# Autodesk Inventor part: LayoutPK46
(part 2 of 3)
    geometry: L1 (-25.4, 4.233)-(0, 0); L2 (0, 0)-(-25.4, -4.233); L3 (-25.4, 4.233)-(-25.4, -4.233); L4 (0, 0)-(-25.4, 0); 1 further point
    constraints: 8 end point, 1 midpoint
  sketch "DatumFilled45_3"
    geometry: L1 (0, 25.4)-(0, -25.4); L2 (0, -25.4)-(-25.4, 0); L3 (-25.4, 0)-(0, 25.4); L4 (0, 25.4)-(0, -25.4); L5 (0, -25.4)-(0, 25.4); L6 (0, 25.4)-(-25.4, 0); L7 (-25.4, 0)-(0, 25.4); 1 further point
    constraints: 14 end point
  sketch "Filled-1_3"
    geometry: L1 (-25.4, 0)-(0, 0); L2 (-25.4, -2.527)-(0, 0); L3 (0, 0)-(-25.4, 2.527); L4 (-25.4, 2.527)-(-25.4, -2.527); L5 (-25.4, -2.527)-(0, 0); L6 (0, 0)-(-25.4, -2.527); L7 (-25.4, -2.527)-(-25.4, 2.527); L8 (-25.4, 2.527)-(-25.4, -2.527); L9 (-25.4, -2.527)-(0, 0); L10 (0, 0)-(-25.4, 2.527); L11 (-25.4, 2.527)-(-25.4, -2.527); 1 further point
    constraints: 22 end point, 4 midpoint
  sketch "Borders Default Border_3"
    geometry: L1 (19.05, 12.7)-(19.05, 419.1); L2 (19.05, 419.1)-(539.75, 419.1); L3 (539.75, 419.1)-(539.75, 12.7); L4 (539.75, 12.7)-(19.05, 12.7); L5 (279.4, 6.35)-(279.4, 12.7); L6 (279.4, 12.7)-(277.2, 8.89); L7 (277.2, 8.89)-(281.6, 8.89); L8 (281.6, 8.89)-(279.4, 12.7); L9 (279.4, 425.45)-(279.4, 419.1); L10 (279.4, 419.1)-(277.2, 422.91); L11 (277.2, 422.91)-(281.6, 422.91); L12 (281.6, 422.91)-(279.4, 419.1); L13 (12.7, 215.9)-(19.05, 215.9); L14 (19.05, 215.9)-(15.24, 218.1); L15 (15.24, 218.1)-(15.24, 213.7); L16 (15.24, 213.7)-(19.05, 215.9); L17 (546.1, 215.9)-(539.75, 215.9); L18 (539.75, 215.9)-(543.56, 218.1); L19 (543.56, 218.1)-(543.56, 213.7); L20 (543.56, 213.7)-(539.75, 215.9); L21 (139.7, 12.7)-(139.7, 8.636); L22 (139.7, 419.1)-(139.7, 423.164); L23 (419.1, 12.7)-(419.1, 8.636); L24 (419.1, 419.1)-(419.1, 423.164); L25 (19.05, 107.95)-(14.986, 107.95); L26 (539.75, 107.95)-(543.814, 107.95); L27 (19.05, 323.85)-(14.986, 323.85); L28 (539.75, 323.85)-(543.814, 323.85); 17 further points
    constraints: 56 end point, 8 point on line, 4 midpoint, 16 other
  sketch "GENAXEH_3"
    geometry: L1 (-25.4, 0)-(25.4, 0); 1 further point
    constraints: 2 end point
  sketch "Weldment_3"
    geometry: L1 (-362.49, 605.558)-(-187.308, 59.988); L2 (-48.402, -559.479)-(-89.17, -792.346); L3 (104.596, -840)-(155.018, -682.036); L4 (176.996, -25.915)-(5.037, 246.17); L5 (5.037, 246.17)-(-175.085, 674.867); L6 (-187.308, 59.988)-(-152.339, -48.916); L7 (-104.241, -121.383)-(-75.352, -146.192); L8 (-8.649, -332.41)-(-48.402, -559.479); L9 (155.018, -682.036)-(230.654, -445.083); L10 (-57.997, -88.254)-(-54.949, -85.206); L11 (-57.997, -85.206)-(-54.949, -88.254); C1 r 75 at (0, 0); C2 r 87 at (0, 0); C3 r 45 at (-267.278, 636.131); C4 r 45 at (9.332, -809.591); C5 r 1.524 at (-56.473, -86.73); A1 r 100 centre (-267.278, 636.131) between (-175.085, 674.867) and (-362.49, 605.558); A2 r 100 centre (9.332, -809.591) between (-89.17, -792.346) and (104.596, -840); A3 r 500 centre (-245.668, -293.04) between (250.28, -356.567) and (176.996, -25.915); A4 r 160 centre (0, 0) between (-152.339, -48.916) and (-104.241, -121.383); A5 r 200 centre (-205.653, -297.921) between (-8.649, -332.41) and (-75.352, -146.192); A6 r 500 centre (-245.668, -293.04) between (230.654, -445.083) and (250.28, -356.567); 1 further point
    constraints: 22 end point, 12 point on circle, 11 centre point
  sketch "Connector_3"
    geometry: L1 (157.164, 27.531)-(232.989, 74.957); L2 (483.604, 231.708)-(512.662, 249.882); L3 (76.449, -64.463)-(145.454, 17.372); L4 (449.028, 351.621)-(398.755, 320.177); L5 (509.104, 419.139)-(460.738, 361.78); L6 (526.921, 255.966)-(571.21, 267.162); L7 (232.989, 74.957)-(483.604, 231.708); L8 (398.755, 320.177)-(93.53, 129.27); L9 (529.743, 443.615)-(509.104, 419.139); L10 (79.271, 123.186)-(-24.509, 96.95); L11 (571.21, 267.162)-(630.701, 282.202); L12 (302.321, 205.82)-(305.369, 208.868); L13 (302.321, 208.868)-(305.369, 205.82); C1 r 45 at (0, 0); C2 r 45 at (606.192, 379.152); C3 r 1.524 at (303.845, 207.344); A1 r 50 centre (539.176, 207.491) between (526.921, 255.966) and (512.662, 249.882); A2 r 50 centre (183.678, -14.86) between (157.164, 27.531) and (145.454, 17.372); A3 r 50 centre (422.514, 394.012) between (449.028, 351.621) and (460.738, 361.78); A4 r 50 centre (67.016, 171.661) between (79.271, 123.186) and (93.53, 129.27); A5 r 100 centre (606.192, 379.152) between (630.701, 282.202) and (529.743, 443.615); A6 r 100 centre (0, 0) between (-24.509, 96.95) and (76.449, -64.463); 1 further point
    constraints: 26 end point, 12 point on circle, 9 centre point
  sketch "Base_3"
    geometry: L1 (278.529, -481.687)-(299.453, -447.453); L2 (295.917, -416.857)-(172.052, -291.319); L3 (95.022, -681.286)-(272.857, -489.184); L4 (108.329, 19.101)-(158.403, -264.884); L5 (-225.117, -660.979)-(-108.413, 18.617); L6 (-225.235, -722.613)-(-225.117, -660.979); L7 (-198.661, -766.881)-(-24.713, -859.13); L8 (3.19, -856.093)-(33.762, -830.109); L9 (48.097, -808.832)-(84.242, -699.551); L10 (0, 254)-(0, -254); L11 (-254, 0)-(254, 0); L12 (0, -346)-(0, -854); L13 (-254, -600)-(254, -600); L14 (37.419, -377.546)-(40.467, -374.498); L15 (37.419, -374.498)-(40.467, -377.546); C1 r 40 at (0, -600); C2 r 40 at (0, 0); C3 r 1.524 at (38.943, -376.022); A1 r 47.5 centre (238, -456.916) between (272.857, -489.184) and (278.529, -481.687); A2 r 25 centre (278.122, -434.416) between (299.453, -447.453) and (295.917, -416.857); A3 r 50 centre (207.644, -256.202) between (158.403, -264.884) and (172.052, -291.319); A4 r 50 centre (-175.235, -722.709) between (-225.235, -722.613) and (-198.661, -766.881); A5 r 50 centre (131.713, -715.252) between (95.022, -681.286) and (84.242, -699.551); A6 r 110 centre (0, 0) between (108.329, 19.101) and (-108.413, 18.617); A7 r 25 centre (-13, -837.043) between (-24.713, -859.13) and (3.19, -856.093); A8 r 47.5 centre (3, -793.916) between (33.762, -830.109) and (48.097, -808.832); 1 further point
    constraints: 30 end point, 16 point on circle, 11 centre point
  sketch "CenterSpan_3"
    geometry: L1 (273.969, -185.044)-(234.974, -284.945); L2 (36.362, 93.155)-(259.933, 5.887); L3 (12.317, -103.462)-(-16.542, -98.622); L4 (180.828, -183.299)-(-38.18, -97.813); L5 (437.598, -26.221)-(296.603, -162.71); L6 (-23.266, 102.39)-(214.339, 156.38); L7 (495.815, 30.136)-(437.598, -26.221); L8 (214.339, 156.38)-(404.104, 199.5); L9 (110.262, -93.996)-(113.31, -90.948); L10 (110.262, -90.948)-(113.31, -93.996); C1 r 82 at (0, 0); C2 r 82 at (223.572, -87.268); C3 r 50 at (426.262, 101.986); C4 r 58.472 at (158.121, -254.947); C5 r 1.524 at (111.786, -92.472); A1 r 90 centre (-2.571, -192.223) between (81.268, -224.948) and (12.317, -103.462); A2 r 60 centre (329.862, -206.861) between (290.003, -162.013) and (273.969, -185.044); A3 r 100 centre (223.572, -87.267) between (290.003, -162.013) and (259.933, 5.887); A4 r 100 centre (0, 0) between (36.362, 93.155) and (-16.542, -98.622); A5 r 105 centre (223.572, -87.268) between (189.942, -186.736) and (296.603, -162.71); A6 r 105 centre (0, 0) between (-23.266, 102.39) and (-38.18, -97.813); A7 r 100 centre (426.262, 101.986) between (495.815, 30.136) and (404.104, 199.5); A8 r 82.5 centre (158.121, -254.946) between (81.268, -224.948) and (234.974, -284.944); 1 further point
    constraints: 20 end point, 17 point on circle, 13 centre point, 1 point on line
  sketch "Arm_3"
    geometry: L1 (-25.496, -107.005)-(137.409, -145.82); L2 (2597.068, -901.099)-(2521.421, -896.025); L3 (2257.231, -771.408)-(2076.35, -579.673); L4 (2076.35, -579.673)-(2063.205, -583.463); L5 (2043.846, -578.704)-(1704.981, -254.849); L6 (1379.251, -95.221)-(16.283, 108.788); L7 (137.409, -145.82)-(1374.243, -440.518); L8 (1601.431, -691.827)-(2199.578, -1052.198); L9 (2469.644, -1123.775)-(2592.355, -1120.82); L10 (1293.329, -509.09)-(1296.377, -506.042); L11 (1293.329, -506.042)-(1296.377, -509.09); C1 r 40.528 at (0, 0); C2 r 40.528 at (2589.706, -1010.852); C3 r 1.524 at (1294.853, -507.566); A1 r 400 centre (2548.19, -496.921) between (2482.623, -891.511) and (2521.421, -896.025); A2 r 110 centre (2589.706, -1010.852) between (2597.994, -1120.539) and (2597.068, -901.099); A3 r 400 centre (2548.19, -496.921) between (2257.231, -771.408) and (2482.623, -891.511); A4 r 20 centre (2057.664, -564.246) between (2043.846, -578.704) and (2063.205, -583.463); A5 r 600 centre (1290.432, -688.61) between (1704.981, -254.849) and (1379.251, -95.221); A6 r 70 centre (1358.018, -508.612) between (1423.227, -534.065) and (1374.243, -440.518); A7 r 100 centre (1516.382, -570.427) between (1423.227, -534.065) and (1519.438, -670.38); A8 r 150 centre (1524.023, -820.31) between (1601.431, -691.827) and (1519.438, -670.38); A9 r 500 centre (2457.606, -623.92) between (2199.578, -1052.198) and (2469.644, -1123.775); A10 r 110 centre (0, 0) between (16.283, 108.788) and (-25.496, -107.005); 1 further point
    constraints: 22 end point, 20 point on circle, 13 centre point
  sketch "Bucket_3"
    geometry: L1 (1144.623, -207.025)-(503.799, -207.025); L2 (963.799, -174.025)-(963.799, -170.025); L3 (503.799, -196.903)-(503.799, -206.906); L4 (503.799, -221.903)-(288.457, -221.903); L5 (288.457, -221.903)-(267.908, -192.554); L6 (513.799, -197.025)-(503.799, -197.025); L7 (1243.799, -187.025)-(1243.799, -177.025); L8 (963.799, -187.025)-(963.799, -162.025); L9 (1144.623, -187.025)-(963.799, -187.025); L10 (963.799, -162.025)-(1213.799, -162.025); L11 (1243.799, -177.025)-(1213.799, -162.025); L12 (787.944, 394.043)-(1129.277, -162.025); L13 (284.259, 704.207)-(293.142, 639.189); L14 (628.799, 940.975)-(308.602, 754.162); L15 (-31.849, -105.289)-(98.676, -144.771); L16 (-48.306, 170.395)-(-101.577, 42.215); L17 (226.161, 631.111)-(211.811, 610.911); L18 (291.393, 651.987)-(226.161, 631.111); L19 (-139.649, 366.255)-(98.676, -144.771); L20 (513.799, -197.025)-(1144.623, -197.025); L21 (513.799, -187.025)-(1144.623, -187.025); L22 (531.254, 866.512)-(201.253, 473.232); L23 (537.781, 858.733)-(208.914, 466.804); L24 (1144.623, -207.025)-(1144.623, -197.025); L25 (1144.623, -197.025)-(1144.623, -187.025); L26 (787.944, 394.043)-(636.196, 915.553); L27 (633.32, 925.44)-(628.799, 940.975); L28 (725.404, 1012.893)-(719.482, 979.31); L29 (735.252, 1011.157)-(729.33, 977.574); L30 (714.634, 972.387)-(531.254, 866.512); L31 (725.404, 1012.893)-(735.252, 1011.157); L32 (1144.623, -187.025)-(1243.799, -187.025); L33 (537.781, 858.733)-(719.634, 963.726); L34 (503.799, -221.903)-(503.799, -206.906); L35 (453.565, -192.554)-(144.85, -192.554); L36 (110.864, -170.904)-(98.676, -144.771); L37 (-78.971, 509.811)-(360.018, 662.44); C1 r 25 at (333.799, 710.975); C2 r 45 at (-44.489, 410.635); A1 r 50 centre (333.799, 710.975) between (308.602, 754.162) and (284.259, 704.207); A2 r 40 centre (0, 0) between (13.62, 37.61) and (37.567, -13.738); A3 r 110 centre (0, 0) between (-101.577, 42.215) and (-31.849, -105.289); A4 r 105 centre (-44.489, 410.635) between (-78.971, 509.811) and (-139.649, 366.255); A5 r 408 centre (513.799, 210.975) between (201.253, 473.232) and (513.799, -197.025); A6 r 398 centre (513.799, 210.975) between (208.914, 466.804) and (513.799, -187.025); A7 r 37.5 centre (144.85, -155.054) between (110.864, -170.904) and (144.85, -192.554); A8 r 10 centre (709.634, 981.047) between (714.634, 972.387) and (719.482, 979.31); A9 r 20 centre (709.634, 981.047) between (719.634, 963.726) and (729.33, 977.574); 1 further point
    constraints: 74 end point, 20 point on circle, 16 point on line, 11 centre point
  sketch "FrontBucket_3"
    geometry: L1 (36.508, 713.207)-(-16.797, 670.2); L2 (-16.797, 670.2)-(-101.739, 335.484); L3 (-101.739, 335.484)-(-109.966, 2.719); L4 (8.288, -109.687)-(308.835, -86.978); L5 (308.835, -86.978)-(319.542, -83.051); L6 (19.324, 520.756)-(99.155, 741.781); L7 (99.155, 741.781)-(80.344, 748.575); L8 (80.344, 748.575)-(36.508, 713.207); L9 (1233.625, 258.517)-(1200.234, 261.682); L10 (1200.234, 261.682)-(1143.868, 239.874); L11 (1143.868, 239.874)-(1177.667, 236.867); L12 (1177.667, 236.867)-(1233.625, 258.517); L13 (967.076, 171.475)-(1143.868, 239.874); L14 (1181.276, 227.541)-(976.097, 148.159); L15 (976.097, 148.159)-(967.076, 171.475); L16 (1237.234, 249.191)-(1233.625, 258.517); L17 (1177.667, 236.867)-(1181.276, 227.541); L18 (1181.276, 227.541)-(1237.234, 249.191); L19 (332.219, -99.88)-(327.869, -88.635); L20 (332.219, -99.88)-(340.093, -96.834); L21 (327.869, -88.635)-(326.446, -84.958); L22 (630.662, 15.585)-(695.946, 40.843); L23 (340.093, -96.834)-(630.662, 15.585); L24 (971.406, 160.283)-(964.544, 144.762); L25 (971.406, 160.283)-(969.963, 164.014); L26 (695.946, 40.843)-(690.173, 55.765); L27 (969.963, 164.014)-(690.173, 55.765); L28 (695.946, 40.843)-(964.544, 144.762); L29 (271.723, 1081.905)-(246.908, 1104.472); L30 (246.908, 1104.472)-(15.69, 814.708); L31 (11.012, 759.335)-(43.462, 700.624); L32 (47.21, 660.849)-(-0.759, 514.651); L33 (556.412, -14.214)-(696.307, 39.911); L34 (696.307, 39.911)-(695.946, 40.843); L35 (594.585, 649.257)-(271.723, 1081.905); L36 (459.694, 596.673)-(459.353, 596.937); L37 (459.353, 596.937)-(498.23, 611.978); L38 (1112.062, 227.901)-(576.694, 642.28); L39 (995.062, 182.294)-(998.041, 183.455); L40 (499.228, 612.083)-(459.694, 596.673); L41 (459.694, 596.673)-(526.939, 544.624); L42 (606.946, 482.699)-(686.952, 420.773); L43 (766.958, 358.848)-(846.965, 296.922); L44 (926.971, 234.997)-(985.819, 189.448); L45 (995.055, 182.3)-(995.062, 182.294); L46 (998.041, 183.455)-(1130.882, 235.237); L47 (985.819, 189.448)-(995.055, 182.3); L48 (1130.882, 235.237)-(595.514, 649.616); C1 r 60 at (0, 0); C2 r 85 at (-189.66, 366.918); C3 r 25 at (54.772, 783.522); C4 r 62.5 at (-189.66, 366.918); A1 r 110 centre (0, 0) between (-109.966, 2.719) and (8.288, -109.687); A2 r 408 centre (403.06, 382.155) between (19.324, 520.756) and (16.94, 513.969); A3 r 50 centre (54.772, 783.522) between (15.69, 814.708) and (11.012, 759.335); A4 r 50 centre (-0.298, 676.437) between (47.21, 660.849) and (43.462, 700.624); A5 r 425 centre (403.06, 382.155) between (-0.759, 514.651) and (556.412, -14.214); 1 further point
    constraints: 96 end point, 10 point on circle, 9 centre point, 6 point on line
  sketch "A$C70327705_2"
    geometry: L1 (1293.342, 14.877)-(652.519, 14.877); L2 (1112.519, 47.877)-(1112.519, 51.877); L3 (652.519, 25)-(652.519, 14.997); L4 (652.519, 0)-(437.177, 0); L5 (437.177, 0)-(416.627, 29.348); L6 (662.519, 24.877)-(652.519, 24.877); L7 (1392.519, 34.877)-(1392.519, 44.877); L8 (1112.519, 34.877)-(1112.519, 59.877); L9 (1293.342, 34.877)-(1112.519, 34.877); L10 (1112.519, 59.877)-(1362.519, 59.877); L11 (1392.519, 44.877)-(1362.519, 59.877); L12 (936.663, 615.946)-(1277.997, 59.877); L13 (432.979, 926.11)-(441.861, 861.091); L14 (777.519, 1162.877)-(457.322, 976.064); L15 (116.871, 116.614)-(247.396, 77.132); L16 (100.413, 392.297)-(47.142, 264.117); L17 (374.881, 853.013)-(360.531, 832.814); L18 (440.113, 873.889)-(374.881, 853.013); L19 (9.07, 588.157)-(247.396, 77.132); L20 (662.519, 24.877)-(1293.342, 24.877); L21 (662.519, 34.877)-(1293.342, 34.877); L22 (679.974, 1088.415)-(349.973, 695.135); L23 (686.501, 1080.636)-(357.633, 688.707); L24 (1293.342, 14.877)-(1293.342, 24.877); L25 (1293.342, 24.877)-(1293.342, 34.877); L26 (936.663, 615.946)-(784.916, 1137.456); L27 (782.039, 1147.342)-(777.519, 1162.877); L28 (874.123, 1234.796)-(868.202, 1201.213); L29 (883.971, 1233.059)-(878.05, 1199.476); L30 (863.354, 1194.289)-(679.974, 1088.415); L31 (874.123, 1234.796)-(883.971, 1233.059); L32 (1293.342, 34.877)-(1392.519, 34.877); L33 (686.501, 1080.636)-(868.354, 1185.629); L34 (652.519, 0)-(652.519, 14.997); L35 (602.285, 29.348)-(293.569, 29.348); L36 (259.584, 50.998)-(247.396, 77.132); L37 (69.748, 731.714)-(508.737, 884.343); C1 r 25 at (482.519, 932.877); C2 r 45 at (104.231, 632.537); A1 r 50 centre (482.519, 932.877) between (457.322, 976.064) and (432.979, 926.11); A2 r 40 centre (148.72, 221.902) between (162.34, 259.512) and (186.286, 208.165); A3 r 110 centre (148.72, 221.902) between (47.142, 264.117) and (116.871, 116.614); A4 r 105 centre (104.231, 632.537) between (69.748, 731.714) and (9.07, 588.157); A5 r 408 centre (662.519, 432.877) between (349.973, 695.135) and (662.519, 24.877); A6 r 398 centre (662.519, 432.877) between (357.633, 688.707) and (662.519, 34.877); A7 r 37.5 centre (293.569, 66.848) between (259.584, 50.998) and (293.569, 29.348); A8 r 10 centre (858.354, 1202.949) between (863.354, 1194.289) and (868.202, 1201.213); A9 r 20 centre (858.354, 1202.949) between (868.354, 1185.629) and (878.05, 1199.476); 1 further point
    constraints: 74 end point, 20 point on circle, 16 point on line, 11 centre point
  sketch "A$C60B60B97_2"
    geometry: 1 further point
  sketch "Borders Default Border_9.00X_3"
    geometry: L1 (171.45, 114.3)-(171.45, 3771.9); L2 (171.45, 3771.9)-(4857.75, 3771.9); L3 (4857.75, 3771.9)-(4857.75, 114.3); L4 (4857.75, 114.3)-(171.45, 114.3); L5 (2514.6, 57.15)-(2514.6, 114.3); L6 (2514.6, 114.3)-(2494.803, 80.01); L7 (2494.803, 80.01)-(2534.397, 80.01); L8 (2534.397, 80.01)-(2514.6, 114.3); L9 (2514.6, 3829.05)-(2514.6, 3771.9); L10 (2514.6, 3771.9)-(2494.803, 3806.19); L11 (2494.803, 3806.19)-(2534.397, 3806.19); L12 (2534.397, 3806.19)-(2514.6, 3771.9); L13 (114.3, 1943.1)-(171.45, 1943.1); L14 (171.45, 1943.1)-(137.16, 1962.897); L15 (137.16, 1962.897)-(137.16, 1923.303); L16 (137.16, 1923.303)-(171.45, 1943.1); L17 (4914.9, 1943.1)-(4857.75, 1943.1); L18 (4857.75, 1943.1)-(4892.04, 1962.897); L19 (4892.04, 1962.897)-(4892.04, 1923.303); L20 (4892.04, 1923.303)-(4857.75, 1943.1); L21 (1257.3, 114.3)-(1257.3, 77.724); L22 (1257.3, 3771.9)-(1257.3, 3808.476); L23 (3771.9, 114.3)-(3771.9, 77.724); L24 (3771.9, 3771.9)-(3771.9, 3808.476); L25 (171.45, 971.55)-(134.874, 971.55); L26 (4857.75, 971.55)-(4894.326, 971.55); L27 (171.45, 2914.65)-(134.874, 2914.65); L28 (4857.75, 2914.65)-(4894.326, 2914.65); 17 further points
    constraints: 56 end point, 8 point on line, 4 midpoint, 16 other
  sketch "_Closed_4"
    geometry: L1 (-25.4, 4.233)-(0, 0); L2 (0, 0)-(-25.4, -4.233); L3 (-25.4, 4.233)-(-25.4, -4.233); L4 (0, 0)-(-25.4, 0); 1 further point
    constraints: 8 end point, 1 midpoint
  sketch "DatumFilled45_4"
    geometry: L1 (0, 25.4)-(0, -25.4); L2 (0, -25.4)-(-25.4, 0); L3 (-25.4, 0)-(0, 25.4); L4 (0, 25.4)-(0, -25.4); L5 (0, -25.4)-(0, 25.4); L6 (0, 25.4)-(-25.4, 0); L7 (-25.4, 0)-(0, 25.4); 1 further point
    constraints: 14 end point
  sketch "Filled-1_4"
    geometry: L1 (-25.4, 0)-(0, 0); L2 (-25.4, -2.527)-(0, 0); L3 (0, 0)-(-25.4, 2.527); L4 (-25.4, 2.527)-(-25.4, -2.527); L5 (-25.4, -2.527)-(0, 0); L6 (0, 0)-(-25.4, -2.527); L7 (-25.4, -2.527)-(-25.4, 2.527); L8 (-25.4, 2.527)-(-25.4, -2.527); L9 (-25.4, -2.527)-(0, 0); L10 (0, 0)-(-25.4, 2.527); L11 (-25.4, 2.527)-(-25.4, -2.527); 1 further point
    constraints: 22 end point, 4 midpoint
  sketch "Borders Default Border_4"
    geometry: L1 (19.05, 12.7)-(19.05, 419.1); L2 (19.05, 419.1)-(539.75, 419.1); L3 (539.75, 419.1)-(539.75, 12.7); L4 (539.75, 12.7)-(19.05, 12.7); L5 (279.4, 6.35)-(279.4, 12.7); L6 (279.4, 12.7)-(277.2, 8.89); L7 (277.2, 8.89)-(281.6, 8.89); L8 (281.6, 8.89)-(279.4, 12.7); L9 (279.4, 425.45)-(279.4, 419.1); L10 (279.4, 419.1)-(277.2, 422.91); L11 (277.2, 422.91)-(281.6, 422.91); L12 (281.6, 422.91)-(279.4, 419.1); L13 (12.7, 215.9)-(19.05, 215.9); L14 (19.05, 215.9)-(15.24, 218.1); L15 (15.24, 218.1)-(15.24, 213.7); L16 (15.24, 213.7)-(19.05, 215.9); L17 (546.1, 215.9)-(539.75, 215.9); L18 (539.75, 215.9)-(543.56, 218.1); L19 (543.56, 218.1)-(543.56, 213.7); L20 (543.56, 213.7)-(539.75, 215.9); L21 (139.7, 12.7)-(139.7, 8.636); L22 (139.7, 419.1)-(139.7, 423.164); L23 (419.1, 12.7)-(419.1, 8.636); L24 (419.1, 419.1)-(419.1, 423.164); L25 (19.05, 107.95)-(14.986, 107.95); L26 (539.75, 107.95)-(543.814, 107.95); L27 (19.05, 323.85)-(14.986, 323.85); L28 (539.75, 323.85)-(543.814, 323.85); 17 further points
    constraints: 56 end point, 8 point on line, 4 midpoint, 16 other
  sketch "GENAXEH_4"
    geometry: L1 (-25.4, 0)-(25.4, 0); 1 further point
    constraints: 2 end point
  sketch "Weldment_4"
    geometry: L1 (-362.49, 605.558)-(-187.308, 59.988); L2 (-48.402, -559.479)-(-89.17, -792.346); L3 (104.596, -840)-(155.018, -682.036); L4 (176.996, -25.915)-(5.037, 246.17); L5 (5.037, 246.17)-(-175.085, 674.867); L6 (-187.308, 59.988)-(-152.339, -48.916); L7 (-104.241, -121.383)-(-75.352, -146.192); L8 (-8.649, -332.41)-(-48.402, -559.479); L9 (155.018, -682.036)-(230.654, -445.083); L10 (-57.997, -88.254)-(-54.949, -85.206); L11 (-57.997, -85.206)-(-54.949, -88.254); C1 r 75 at (0, 0); C2 r 87 at (0, 0); C3 r 45 at (-267.278, 636.131); C4 r 45 at (9.332, -809.591); C5 r 1.524 at (-56.473, -86.73); A1 r 100 centre (-267.278, 636.131) between (-175.085, 674.867) and (-362.49, 605.558); A2 r 100 centre (9.332, -809.591) between (-89.17, -792.346) and (104.596, -840); A3 r 500 centre (-245.668, -293.04) between (250.28, -356.567) and (176.996, -25.915); A4 r 160 centre (0, 0) between (-152.339, -48.916) and (-104.241, -121.383); A5 r 200 centre (-205.653, -297.921) between (-8.649, -332.41) and (-75.352, -146.192); A6 r 500 centre (-245.668, -293.04) between (230.654, -445.083) and (250.28, -356.567); 1 further point
    constraints: 22 end point, 12 point on circle, 11 centre point
  sketch "Connector_4"
    geometry: L1 (157.164, 27.531)-(232.989, 74.957); L2 (483.604, 231.708)-(512.662, 249.882); L3 (76.449, -64.463)-(145.454, 17.372); L4 (449.028, 351.621)-(398.755, 320.177); L5 (509.104, 419.139)-(460.738, 361.78); L6 (526.921, 255.966)-(571.21, 267.162); L7 (232.989, 74.957)-(483.604, 231.708); L8 (398.755, 320.177)-(93.53, 129.27); L9 (529.743, 443.615)-(509.104, 419.139); L10 (79.271, 123.186)-(-24.509, 96.95); L11 (571.21, 267.162)-(630.701, 282.202); L12 (302.321, 205.82)-(305.369, 208.868); L13 (302.321, 208.868)-(305.369, 205.82); C1 r 45 at (0, 0); C2 r 45 at (606.192, 379.152); C3 r 1.524 at (303.845, 207.344); A1 r 50 centre (539.176, 207.491) between (526.921, 255.966) and (512.662, 249.882); A2 r 50 centre (183.678, -14.86) between (157.164, 27.531) and (145.454, 17.372); A3 r 50 centre (422.514, 394.012) between (449.028, 351.621) and (460.738, 361.78); A4 r 50 centre (67.016, 171.661) between (79.271, 123.186) and (93.53, 129.27); A5 r 100 centre (606.192, 379.152) between (630.701, 282.202) and (529.743, 443.615); A6 r 100 centre (0, 0) between (-24.509, 96.95) and (76.449, -64.463); 1 further point
    constraints: 26 end point, 12 point on circle, 9 centre point
  sketch "Base_4"
    geometry: L1 (278.529, -481.687)-(299.453, -447.453); L2 (295.917, -416.857)-(172.052, -291.319); L3 (95.022, -681.286)-(272.857, -489.184); L4 (108.329, 19.101)-(158.403, -264.884); L5 (-225.117, -660.979)-(-108.413, 18.617); L6 (-225.235, -722.613)-(-225.117, -660.979); L7 (-198.661, -766.881)-(-24.713, -859.13); L8 (3.19, -856.093)-(33.762, -830.109); L9 (48.097, -808.832)-(84.242, -699.551); L10 (0, 254)-(0, -254); L11 (-254, 0)-(254, 0); L12 (0, -346)-(0, -854); L13 (-254, -600)-(254, -600); L14 (37.419, -377.546)-(40.467, -374.498); L15 (37.419, -374.498)-(40.467, -377.546); C1 r 40 at (0, -600); C2 r 40 at (0, 0); C3 r 1.524 at (38.943, -376.022); A1 r 47.5 centre (238, -456.916) between (272.857, -489.184) and (278.529, -481.687); A2 r 25 centre (278.122, -434.416) between (299.453, -447.453) and (295.917, -416.857); A3 r 50 centre (207.644, -256.202) between (158.403, -264.884) and (172.052, -291.319); A4 r 50 centre (-175.235, -722.709) between (-225.235, -722.613) and (-198.661, -766.881); A5 r 50 centre (131.713, -715.252) between (95.022, -681.286) and (84.242, -699.551); A6 r 110 centre (0, 0) between (108.329, 19.101) and (-108.413, 18.617); A7 r 25 centre (-13, -837.043) between (-24.713, -859.13) and (3.19, -856.093); A8 r 47.5 centre (3, -793.916) between (33.762, -830.109) and (48.097, -808.832); 1 further point
    constraints: 30 end point, 16 point on circle, 11 centre point
  sketch "CenterSpan_4"
    geometry: L1 (273.969, -185.044)-(234.974, -284.945); L2 (36.362, 93.155)-(259.933, 5.887); L3 (12.317, -103.462)-(-16.542, -98.622); L4 (180.828, -183.299)-(-38.18, -97.813); L5 (437.598, -26.221)-(296.603, -162.71); L6 (-23.266, 102.39)-(214.339, 156.38); L7 (495.815, 30.136)-(437.598, -26.221); L8 (214.339, 156.38)-(404.104, 199.5); L9 (110.262, -93.996)-(113.31, -90.948); L10 (110.262, -90.948)-(113.31, -93.996); C1 r 82 at (0, 0); C2 r 82 at (223.572, -87.268); C3 r 50 at (426.262, 101.986); C4 r 58.472 at (158.121, -254.947); C5 r 1.524 at (111.786, -92.472); A1 r 90 centre (-2.571, -192.223) between (81.268, -224.948) and (12.317, -103.462); A2 r 60 centre (329.862, -206.861) between (290.003, -162.013) and (273.969, -185.044); A3 r 100 centre (223.572, -87.267) between (290.003, -162.013) and (259.933, 5.887); A4 r 100 centre (0, 0) between (36.362, 93.155) and (-16.542, -98.622); A5 r 105 centre (223.572, -87.268) between (189.942, -186.736) and (296.603, -162.71); A6 r 105 centre (0, 0) between (-23.266, 102.39) and (-38.18, -97.813); A7 r 100 centre (426.262, 101.986) between (495.815, 30.136) and (404.104, 199.5); A8 r 82.5 centre (158.121, -254.946) between (81.268, -224.948) and (234.974, -284.944); 1 further point
    constraints: 20 end point, 17 point on circle, 13 centre point, 1 point on line
  sketch "Arm_4"
    geometry: L1 (-25.496, -107.005)-(137.409, -145.82); L2 (2597.068, -901.099)-(2521.421, -896.025); L3 (2257.231, -771.408)-(2076.35, -579.673); L4 (2076.35, -579.673)-(2063.205, -583.463); L5 (2043.846, -578.704)-(1704.981, -254.849); L6 (1379.251, -95.221)-(16.283, 108.788); L7 (137.409, -145.82)-(1374.243, -440.518); L8 (1601.431, -691.827)-(2199.578, -1052.198); L9 (2469.644, -1123.775)-(2592.355, -1120.82); L10 (1293.329, -509.09)-(1296.377, -506.042); L11 (1293.329, -506.042)-(1296.377, -509.09); C1 r 40.528 at (0, 0); C2 r 40.528 at (2589.706, -1010.852); C3 r 1.524 at (1294.853, -507.566); A1 r 400 centre (2548.19, -496.921) between (2482.623, -891.511) and (2521.421, -896.025); A2 r 110 centre (2589.706, -1010.852) between (2597.994, -1120.539) and (2597.068, -901.099); A3 r 400 centre (2548.19, -496.921) between (2257.231, -771.408) and (2482.623, -891.511); A4 r 20 centre (2057.664, -564.246) between (2043.846, -578.704) and (2063.205, -583.463); A5 r 600 centre (1290.432, -688.61) between (1704.981, -254.849) and (1379.251, -95.221); A6 r 70 centre (1358.018, -508.612) between (1423.227, -534.065) and (1374.243, -440.518); A7 r 100 centre (1516.382, -570.427) between (1423.227, -534.065) and (1519.438, -670.38); A8 r 150 centre (1524.023, -820.31) between (1601.431, -691.827) and (1519.438, -670.38); A9 r 500 centre (2457.606, -623.92) between (2199.578, -1052.198) and (2469.644, -1123.775); A10 r 110 centre (0, 0) between (16.283, 108.788) and (-25.496, -107.005); 1 further point
    constraints: 22 end point, 20 point on circle, 13 centre point
  sketch "Bucket_4"
    geometry: L1 (0, -20)-(-640.824, -20); L2 (-180.824, 13)-(-180.824, 17); L3 (-640.824, -9.877)-(-640.824, -19.88); L4 (-640.824, -34.877)-(-856.165, -34.877); L5 (-856.165, -34.877)-(-876.715, -5.529); L6 (-630.824, -10)-(-640.824, -10); L7 (99.176, 0)-(99.176, 10); L8 (-180.824, 0)-(-180.824, 25); L9 (0, 0)-(-180.824, 0); L10 (-180.824, 25)-(69.176, 25); L11 (99.176, 10)-(69.176, 25); L12 (-356.679, 581.068)-(-15.346, 25); L13 (-860.363, 891.232)-(-851.481, 826.214); L14 (-515.824, 1128)-(-836.02, 941.187); L15 (-1176.471, 81.737)-(-1045.947, 42.254); L16 (-1192.929, 357.42)-(-1246.2, 229.24); L17 (-918.462, 818.136)-(-932.812, 797.937); L18 (-853.23, 839.012)-(-918.462, 818.136); L19 (-1284.272, 553.28)-(-1045.947, 42.254); L20 (-630.824, -10)-(0, -10); L21 (-630.824, 0)-(0, 0); L22 (-613.369, 1053.537)-(-943.37, 660.257); L23 (-606.842, 1045.759)-(-935.709, 653.829); L24 (0, -20)-(0, -10); L25 (0, -10)-(0, 0); L26 (-356.679, 581.068)-(-508.427, 1102.579); L27 (-511.303, 1112.465)-(-515.824, 1128); L28 (-419.219, 1199.918)-(-425.141, 1166.336); L29 (-409.371, 1198.182)-(-415.292, 1164.599); L30 (-429.989, 1159.412)-(-613.369, 1053.537); L31 (-419.219, 1199.918)-(-409.371, 1198.182); L32 (0, 0)-(99.176, 0); L33 (-606.842, 1045.759)-(-424.989, 1150.752); L34 (-640.824, -34.877)-(-640.824, -19.88); L35 (-691.058, -5.529)-(-999.773, -5.529); L36 (-1033.759, 16.121)-(-1045.947, 42.254); L37 (-1223.594, 696.836)-(-784.605, 849.466); C1 r 25 at (-810.824, 898); C2 r 45 at (-1189.112, 597.66); A1 r 50 centre (-810.824, 898) between (-836.02, 941.187) and (-860.363, 891.232); A2 r 40 centre (-1144.623, 187.025) between (-1131.003, 224.635) and (-1107.056, 173.287); A3 r 110 centre (-1144.623, 187.025) between (-1246.2, 229.24) and (-1176.471, 81.737); A4 r 105 centre (-1189.112, 597.66) between (-1223.594, 696.836) and (-1284.272, 553.28); A5 r 408 centre (-630.824, 398) between (-943.37, 660.257) and (-630.824, -10); A6 r 398 centre (-630.824, 398) between (-935.709, 653.829) and (-630.824, 0); A7 r 37.5 centre (-999.773, 31.971) between (-1033.759, 16.121) and (-999.773, -5.529); A8 r 10 centre (-434.989, 1168.072) between (-429.989, 1159.412) and (-425.141, 1166.336); A9 r 20 centre (-434.989, 1168.072) between (-424.989, 1150.752) and (-415.292, 1164.599); 1 further point
    constraints: 74 end point, 20 point on circle, 16 point on line, 11 centre point
  sketch "FrontBucket_4"
    geometry: L1 (36.508, 713.207)-(-16.797, 670.2); L2 (-16.797, 670.2)-(-101.739, 335.484); L3 (-101.739, 335.484)-(-109.966, 2.719); L4 (8.288, -109.687)-(308.835, -86.978); L5 (308.835, -86.978)-(319.542, -83.051); L6 (19.324, 520.756)-(99.155, 741.781); L7 (99.155, 741.781)-(80.344, 748.575); L8 (80.344, 748.575)-(36.508, 713.207); L9 (1233.625, 258.517)-(1200.234, 261.682); L10 (1200.234, 261.682)-(1143.868, 239.874); L11 (1143.868, 239.874)-(1177.667, 236.867); L12 (1177.667, 236.867)-(1233.625, 258.517); L13 (967.076, 171.475)-(1143.868, 239.874); L14 (1181.276, 227.541)-(976.097, 148.159); L15 (976.097, 148.159)-(967.076, 171.475); L16 (1237.234, 249.191)-(1233.625, 258.517); L17 (1177.667, 236.867)-(1181.276, 227.541); L18 (1181.276, 227.541)-(1237.234, 249.191); L19 (332.219, -99.88)-(327.869, -88.635); L20 (332.219, -99.88)-(340.093, -96.834); L21 (327.869, -88.635)-(326.446, -84.958); L22 (630.662, 15.585)-(695.946, 40.843); L23 (340.093, -96.834)-(630.662, 15.585); L24 (971.406, 160.283)-(964.544, 144.762); L25 (971.406, 160.283)-(969.963, 164.014); L26 (695.946, 40.843)-(690.173, 55.765); L27 (969.963, 164.014)-(690.173, 55.765); L28 (695.946, 40.843)-(964.544, 144.762); L29 (271.723, 1081.905)-(246.908, 1104.472); L30 (246.908, 1104.472)-(15.69, 814.708); L31 (11.012, 759.335)-(43.462, 700.624); L32 (47.21, 660.849)-(-0.759, 514.651); L33 (556.412, -14.214)-(696.307, 39.911); L34 (696.307, 39.911)-(695.946, 40.843); L35 (594.585, 649.257)-(271.723, 1081.905); L36 (459.694, 596.673)-(459.353, 596.937); L37 (459.353, 596.937)-(498.23, 611.978); L38 (1112.062, 227.901)-(576.694, 642.28); L39 (995.062, 182.294)-(998.041, 183.455); L40 (499.228, 612.083)-(459.694, 596.673); L41 (459.694, 596.673)-(526.939, 544.624); L42 (606.946, 482.699)-(686.952, 420.773); L43 (766.958, 358.848)-(846.965, 296.922); L44 (926.971, 234.997)-(985.819, 189.448); L45 (995.055, 182.3)-(995.062, 182.294); L46 (998.041, 183.455)-(1130.882, 235.237); L47 (985.819, 189.448)-(995.055, 182.3); L48 (1130.882, 235.237)-(595.514, 649.616); C1 r 60 at (0, 0); C2 r 85 at (-189.66, 366.918); C3 r 25 at (54.772, 783.522); C4 r 62.5 at (-189.66, 366.918); A1 r 110 centre (0, 0) between (-109.966, 2.719) and (8.288, -109.687); A2 r 408 centre (403.06, 382.155) between (19.324, 520.756) and (16.94, 513.969); A3 r 50 centre (54.772, 783.522) between (15.69, 814.708) and (11.012, 759.335); A4 r 50 centre (-0.298, 676.437) between (47.21, 660.849) and (43.462, 700.624); A5 r 425 centre (403.06, 382.155) between (-0.759, 514.651) and (556.412, -14.214); 1 further point
    constraints: 96 end point, 10 point on circle, 9 centre point, 6 point on line
  sketch "A$C70327705_3"
    geometry: L1 (1293.342, 14.877)-(652.519, 14.877); L2 (1112.519, 47.877)-(1112.519, 51.877); L3 (652.519, 25)-(652.519, 14.997); L4 (652.519, 0)-(437.177, 0); L5 (437.177, 0)-(416.627, 29.348); L6 (662.519, 24.877)-(652.519, 24.877); L7 (1392.519, 34.877)-(1392.519, 44.877); L8 (1112.519, 34.877)-(1112.519, 59.877); L9 (1293.342, 34.877)-(1112.519, 34.877); L10 (1112.519, 59.877)-(1362.519, 59.877); L11 (1392.519, 44.877)-(1362.519, 59.877); L12 (936.663, 615.946)-(1277.997, 59.877); L13 (432.979, 926.11)-(441.861, 861.091); L14 (777.519, 1162.877)-(457.322, 976.064); L15 (116.871, 116.614)-(247.396, 77.132); L16 (100.413, 392.297)-(47.142, 264.117); L17 (374.881, 853.013)-(360.531, 832.814); L18 (440.113, 873.889)-(374.881, 853.013); L19 (9.07, 588.157)-(247.396, 77.132); L20 (662.519, 24.877)-(1293.342, 24.877); L21 (662.519, 34.877)-(1293.342, 34.877); L22 (679.974, 1088.415)-(349.973, 695.135); L23 (686.501, 1080.636)-(357.633, 688.707); L24 (1293.342, 14.877)-(1293.342, 24.877); L25 (1293.342, 24.877)-(1293.342, 34.877); L26 (936.663, 615.946)-(784.916, 1137.456); L27 (782.039, 1147.342)-(777.519, 1162.877); L28 (874.123, 1234.796)-(868.202, 1201.213); L29 (883.971, 1233.059)-(878.05, 1199.476); L30 (863.354, 1194.289)-(679.974, 1088.415); L31 (874.123, 1234.796)-(883.971, 1233.059); L32 (1293.342, 34.877)-(1392.519, 34.877); L33 (686.501, 1080.636)-(868.354, 1185.629); L34 (652.519, 0)-(652.519, 14.997); L35 (602.285, 29.348)-(293.569, 29.348); L36 (259.584, 50.998)-(247.396, 77.132); L37 (69.748, 731.714)-(508.737, 884.343); C1 r 25 at (482.519, 932.877); C2 r 45 at (104.231, 632.537); A1 r 50 centre (482.519, 932.877) between (457.322, 976.064) and (432.979, 926.11); A2 r 40 centre (148.72, 221.902) between (162.34, 259.512) and (186.286, 208.165); A3 r 110 centre (148.72, 221.902) between (47.142, 264.117) and (116.871, 116.614); A4 r 105 centre (104.231, 632.537) between (69.748, 731.714) and (9.07, 588.157); A5 r 408 centre (662.519, 432.877) between (349.973, 695.135) and (662.519, 24.877); A6 r 398 centre (662.519, 432.877) between (357.633, 688.707) and (662.519, 34.877); A7 r 37.5 centre (293.569, 66.848) between (259.584, 50.998) and (293.569, 29.348); A8 r 10 centre (858.354, 1202.949) between (863.354, 1194.289) and (868.202, 1201.213); A9 r 20 centre (858.354, 1202.949) between (868.354, 1185.629) and (878.05, 1199.476); 1 further point
    constraints: 74 end point, 20 point on circle, 16 point on line, 11 centre point
  sketch "A$C60B60B97_3"
    geometry: 1 further point
  sketch "Borders Default Border_9.00X_4"
    geometry: L1 (171.45, 114.3)-(171.45, 3771.9); L2 (171.45, 3771.9)-(4857.75, 3771.9); L3 (4857.75, 3771.9)-(4857.75, 114.3); L4 (4857.75, 114.3)-(171.45, 114.3); L5 (2514.6, 57.15)-(2514.6, 114.3); L6 (2514.6, 114.3)-(2494.803, 80.01); L7 (2494.803, 80.01)-(2534.397, 80.01); L8 (2534.397, 80.01)-(2514.6, 114.3); L9 (2514.6, 3829.05)-(2514.6, 3771.9); L10 (2514.6, 3771.9)-(2494.803, 3806.19); L11 (2494.803, 3806.19)-(2534.397, 3806.19); L12 (2534.397, 3806.19)-(2514.6, 3771.9); L13 (114.3, 1943.1)-(171.45, 1943.1); L14 (171.45, 1943.1)-(137.16, 1962.897); L15 (137.16, 1962.897)-(137.16, 1923.303); L16 (137.16, 1923.303)-(171.45, 1943.1); L17 (4914.9, 1943.1)-(4857.75, 1943.1); L18 (4857.75, 1943.1)-(4892.04, 1962.897); L19 (4892.04, 1962.897)-(4892.04, 1923.303); L20 (4892.04, 1923.303)-(4857.75, 1943.1); L21 (1257.3, 114.3)-(1257.3, 77.724); L22 (1257.3, 3771.9)-(1257.3, 3808.476); L23 (3771.9, 114.3)-(3771.9, 77.724); L24 (3771.9, 3771.9)-(3771.9, 3808.476); L25 (171.45, 971.55)-(134.874, 971.55); L26 (4857.75, 971.55)-(4894.326, 971.55); L27 (171.45, 2914.65)-(134.874, 2914.65); L28 (4857.75, 2914.65)-(4894.326, 2914.65); 17 further points
    constraints: 56 end point, 8 point on line, 4 midpoint, 16 other
  sketch "_Closed_5"
    geometry: L1 (-25.4, 4.233)-(0, 0); L2 (0, 0)-(-25.4, -4.233); L3 (-25.4, 4.233)-(-25.4, -4.233); L4 (0, 0)-(-25.4, 0); 1 further point
    constraints: 8 end point, 1 midpoint
  sketch "DatumFilled45_5"
    geometry: L1 (0, 25.4)-(0, -25.4); L2 (0, -25.4)-(-25.4, 0); L3 (-25.4, 0)-(0, 25.4); L4 (0, 25.4)-(0, -25.4); L5 (0, -25.4)-(0, 25.4); L6 (0, 25.4)-(-25.4, 0); L7 (-25.4, 0)-(0, 25.4); 1 further point
    constraints: 14 end point
  sketch "Filled-1_5"
    geometry: L1 (-25.4, 0)-(0, 0); L2 (-25.4, -2.527)-(0, 0); L3 (0, 0)-(-25.4, 2.527); L4 (-25.4, 2.527)-(-25.4, -2.527); L5 (-25.4, -2.527)-(0, 0); L6 (0, 0)-(-25.4, -2.527); L7 (-25.4, -2.527)-(-25.4, 2.527); L8 (-25.4, 2.527)-(-25.4, -2.527); L9 (-25.4, -2.527)-(0, 0); L10 (0, 0)-(-25.4, 2.527); L11 (-25.4, 2.527)-(-25.4, -2.527); 1 further point
    constraints: 22 end point, 4 midpoint
  sketch "Borders Default Border_5"
    geometry: L1 (19.05, 12.7)-(19.05, 419.1); L2 (19.05, 419.1)-(539.75, 419.1); L3 (539.75, 419.1)-(539.75, 12.7); L4 (539.75, 12.7)-(19.05, 12.7); L5 (279.4, 6.35)-(279.4, 12.7); L6 (279.4, 12.7)-(277.2, 8.89); L7 (277.2, 8.89)-(281.6, 8.89); L8 (281.6, 8.89)-(279.4, 12.7); L9 (279.4, 425.45)-(279.4, 419.1); L10 (279.4, 419.1)-(277.2, 422.91); L11 (277.2, 422.91)-(281.6, 422.91); L12 (281.6, 422.91)-(279.4, 419.1); L13 (12.7, 215.9)-(19.05, 215.9); L14 (19.05, 215.9)-(15.24, 218.1); L15 (15.24, 218.1)-(15.24, 213.7); L16 (15.24, 213.7)-(19.05, 215.9); L17 (546.1, 215.9)-(539.75, 215.9); L18 (539.75, 215.9)-(543.56, 218.1); L19 (543.56, 218.1)-(543.56, 213.7); L20 (543.56, 213.7)-(539.75, 215.9); L21 (139.7, 12.7)-(139.7, 8.636); L22 (139.7, 419.1)-(139.7, 423.164); L23 (419.1, 12.7)-(419.1, 8.636); L24 (419.1, 419.1)-(419.1, 423.164); L25 (19.05, 107.95)-(14.986, 107.95); L26 (539.75, 107.95)-(543.814, 107.95); L27 (19.05, 323.85)-(14.986, 323.85); L28 (539.75, 323.85)-(543.814, 323.85); 17 further points
    constraints: 56 end point, 8 point on line, 4 midpoint, 16 other
  sketch "GENAXEH_5"
    geometry: L1 (-25.4, 0)-(25.4, 0); 1 further point
    constraints: 2 end point
  sketch "Weldment_5"
    geometry: L1 (-362.49, 605.558)-(-187.308, 59.988); L2 (-48.402, -559.479)-(-89.17, -792.346); L3 (104.596, -840)-(155.018, -682.036); L4 (176.996, -25.915)-(5.037, 246.17); L5 (5.037, 246.17)-(-175.085, 674.867); L6 (-187.308, 59.988)-(-152.339, -48.916); L7 (-104.241, -121.383)-(-75.352, -146.192); L8 (-8.649, -332.41)-(-48.402, -559.479); L9 (155.018, -682.036)-(230.654, -445.083); L10 (-57.997, -88.254)-(-54.949, -85.206); L11 (-57.997, -85.206)-(-54.949, -88.254); C1 r 75 at (0, 0); C2 r 87 at (0, 0); C3 r 45 at (-267.278, 636.131); C4 r 45 at (9.332, -809.591); C5 r 1.524 at (-56.473, -86.73); A1 r 100 centre (-267.278, 636.131) between (-175.085, 674.867) and (-362.49, 605.558); A2 r 100 centre (9.332, -809.591) between (-89.17, -792.346) and (104.596, -840); A3 r 500 centre (-245.668, -293.04) between (250.28, -356.567) and (176.996, -25.915); A4 r 160 centre (0, 0) between (-152.339, -48.916) and (-104.241, -121.383); A5 r 200 centre (-205.653, -297.921) between (-8.649, -332.41) and (-75.352, -146.192); A6 r 500 centre (-245.668, -293.04) between (230.654, -445.083) and (250.28, -356.567); 1 further point
    constraints: 22 end point, 12 point on circle, 11 centre point
  sketch "Connector_5"
    geometry: L1 (157.164, 27.531)-(232.989, 74.957); L2 (483.604, 231.708)-(512.662, 249.882); L3 (76.449, -64.463)-(145.454, 17.372); L4 (449.028, 351.621)-(398.755, 320.177); L5 (509.104, 419.139)-(460.738, 361.78); L6 (526.921, 255.966)-(571.21, 267.162); L7 (232.989, 74.957)-(483.604, 231.708); L8 (398.755, 320.177)-(93.53, 129.27); L9 (529.743, 443.615)-(509.104, 419.139); L10 (79.271, 123.186)-(-24.509, 96.95); L11 (571.21, 267.162)-(630.701, 282.202); L12 (302.321, 205.82)-(305.369, 208.868); L13 (302.321, 208.868)-(305.369, 205.82); C1 r 45 at (0, 0); C2 r 45 at (606.192, 379.152); C3 r 1.524 at (303.845, 207.344); A1 r 50 centre (539.176, 207.491) between (526.921, 255.966) and (512.662, 249.882); A2 r 50 centre (183.678, -14.86) between (157.164, 27.531) and (145.454, 17.372); A3 r 50 centre (422.514, 394.012) between (449.028, 351.621) and (460.738, 361.78); A4 r 50 centre (67.016, 171.661) between (79.271, 123.186) and (93.53, 129.27); A5 r 100 centre (606.192, 379.152) between (630.701, 282.202) and (529.743, 443.615); A6 r 100 centre (0, 0) between (-24.509, 96.95) and (76.449, -64.463); 1 further point
    constraints: 26 end point, 12 point on circle, 9 centre point
  sketch "Base_5"
    geometry: L1 (278.529, -481.687)-(299.453, -447.453); L2 (295.917, -416.857)-(172.052, -291.319); L3 (95.022, -681.286)-(272.857, -489.184); L4 (108.329, 19.101)-(158.403, -264.884); L5 (-225.117, -660.979)-(-108.413, 18.617); L6 (-225.235, -722.613)-(-225.117, -660.979); L7 (-198.661, -766.881)-(-24.713, -859.13); L8 (3.19, -856.093)-(33.762, -830.109); L9 (48.097, -808.832)-(84.242, -699.551); L10 (0, 254)-(0, -254); L11 (-254, 0)-(254, 0); L12 (0, -346)-(0, -854); L13 (-254, -600)-(254, -600); L14 (37.419, -377.546)-(40.467, -374.498); L15 (37.419, -374.498)-(40.467, -377.546); C1 r 40 at (0, -600); C2 r 40 at (0, 0); C3 r 1.524 at (38.943, -376.022); A1 r 47.5 centre (238, -456.916) between (272.857, -489.184) and (278.529, -481.687); A2 r 25 centre (278.122, -434.416) between (299.453, -447.453) and (295.917, -416.857); A3 r 50 centre (207.644, -256.202) between (158.403, -264.884) and (172.052, -291.319); A4 r 50 centre (-175.235, -722.709) between (-225.235, -722.613) and (-198.661, -766.881); A5 r 50 centre (131.713, -715.252) between (95.022, -681.286) and (84.242, -699.551); A6 r 110 centre (0, 0) between (108.329, 19.101) and (-108.413, 18.617); A7 r 25 centre (-13, -837.043) between (-24.713, -859.13) and (3.19, -856.093); A8 r 47.5 centre (3, -793.916) between (33.762, -830.109) and (48.097, -808.832); 1 further point
    constraints: 30 end point, 16 point on circle, 11 centre point
  sketch "CenterSpan_5"
    geometry: L1 (273.969, -185.044)-(234.974, -284.945); L2 (36.362, 93.155)-(259.933, 5.887); L3 (12.317, -103.462)-(-16.542, -98.622); L4 (180.828, -183.299)-(-38.18, -97.813); L5 (437.598, -26.221)-(296.603, -162.71); L6 (-23.266, 102.39)-(214.339, 156.38); L7 (495.815, 30.136)-(437.598, -26.221); L8 (214.339, 156.38)-(404.104, 199.5); L9 (110.262, -93.996)-(113.31, -90.948); L10 (110.262, -90.948)-(113.31, -93.996); C1 r 82 at (0, 0); C2 r 82 at (223.572, -87.268); C3 r 50 at (426.262, 101.986); C4 r 58.472 at (158.121, -254.947); C5 r 1.524 at (111.786, -92.472); A1 r 90 centre (-2.571, -192.223) between (81.268, -224.948) and (12.317, -103.462); A2 r 60 centre (329.862, -206.861) between (290.003, -162.013) and (273.969, -185.044); A3 r 100 centre (223.572, -87.267) between (290.003, -162.013) and (259.933, 5.887); A4 r 100 centre (0, 0) between (36.362, 93.155) and (-16.542, -98.622); A5 r 105 centre (223.572, -87.268) between (189.942, -186.736) and (296.603, -162.71); A6 r 105 centre (0, 0) between (-23.266, 102.39) and (-38.18, -97.813); A7 r 100 centre (426.262, 101.986) between (495.815, 30.136) and (404.104, 199.5); A8 r 82.5 centre (158.121, -254.946) between (81.268, -224.948) and (234.974, -284.944); 1 further point
    constraints: 20 end point, 17 point on circle, 13 centre point, 1 point on line
  sketch "Arm_5"
    geometry: L1 (-25.496, -107.005)-(137.409, -145.82); L2 (2597.068, -901.099)-(2521.421, -896.025); L3 (2257.231, -771.408)-(2076.35, -579.673); L4 (2076.35, -579.673)-(2063.205, -583.463); L5 (2043.846, -578.704)-(1704.981, -254.849); L6 (1379.251, -95.221)-(16.283, 108.788); L7 (137.409, -145.82)-(1374.243, -440.518); L8 (1601.431, -691.827)-(2199.578, -1052.198); L9 (2469.644, -1123.775)-(2592.355, -1120.82); L10 (1293.329, -509.09)-(1296.377, -506.042); L11 (1293.329, -506.042)-(1296.377, -509.09); C1 r 40.528 at (0, 0); C2 r 40.528 at (2589.706, -1010.852); C3 r 1.524 at (1294.853, -507.566); A1 r 400 centre (2548.19, -496.921) between (2482.623, -891.511) and (2521.421, -896.025); A2 r 110 centre (2589.706, -1010.852) between (2597.994, -1120.539) and (2597.068, -901.099); A3 r 400 centre (2548.19, -496.921) between (2257.231, -771.408) and (2482.623, -891.511); A4 r 20 centre (2057.664, -564.246) between (2043.846, -578.704) and (2063.205, -583.463); A5 r 600 centre (1290.432, -688.61) between (1704.981, -254.849) and (1379.251, -95.221); A6 r 70 centre (1358.018, -508.612) between (1423.227, -534.065) and (1374.243, -440.518); A7 r 100 centre (1516.382, -570.427) between (1423.227, -534.065) and (1519.438, -670.38); A8 r 150 centre (1524.023, -820.31) between (1601.431, -691.827) and (1519.438, -670.38); A9 r 500 centre (2457.606, -623.92) between (2199.578, -1052.198) and (2469.644, -1123.775); A10 r 110 centre (0, 0) between (16.283, 108.788) and (-25.496, -107.005); 1 further point
    constraints: 22 end point, 20 point on circle, 13 centre point
  sketch "Bucket_5"
    geometry: L1 (0, -20)-(-640.824, -20); L2 (-180.824, 13)-(-180.824, 17); L3 (99.176, 0)-(99.176, 10); L4 (-180.824, 0)-(-180.824, 25); L5 (0, 0)-(-180.824, 0); L6 (-180.824, 25)-(69.176, 25); L7 (99.176, 10)-(69.176, 25); L8 (-356.679, 581.068)-(-15.346, 25); L9 (-860.363, 891.232)-(-851.481, 826.214); L10 (-515.824, 1128)-(-836.02, 941.187); L11 (-1192.929, 357.42)-(-1246.2, 229.24); L12 (-1284.272, 553.28)-(-1045.947, 42.254); L13 (-630.824, -10)-(0, -10); L14 (-630.824, 0)-(0, 0); L15 (-613.369, 1053.537)-(-943.37, 660.257); L16 (-606.842, 1045.759)-(-935.709, 653.829); L17 (0, -20)-(0, -10); L18 (0, -10)-(0, 0); L19 (-356.679, 581.068)-(-508.427, 1102.579); L20 (-511.303, 1112.465)-(-515.824, 1128); L21 (-419.219, 1199.918)-(-425.141, 1166.336); L22 (-409.371, 1198.182)-(-415.292, 1164.599); L23 (-429.989, 1159.412)-(-613.369, 1053.537); L24 (-419.219, 1199.918)-(-409.371, 1198.182); L25 (0, 0)-(99.176, 0); L26 (-606.842, 1045.759)-(-424.989, 1150.752); L27 (-691.058, -5.529)-(-999.773, -5.529); L28 (-1033.759, 16.121)-(-1045.947, 42.254); L29 (-1223.594, 696.836)-(-784.605, 849.466); L30 (-1176.471, 81.737)-(-1045.947, 42.254); L31 (-1045.947, 42.254)-(-887.978, -5.529); L32 (-785.809, 848.032)-(-1117.669, 537.354); L33 (-1192.929, 357.42)-(-1118.456, 536.618); C1 r 25 at (-810.824, 898); C2 r 45 at (-1189.112, 597.66); A1 r 50 centre (-810.824, 898) between (-836.02, 941.187) and (-860.363, 891.232); A2 r 40 centre (-1144.623, 187.025) between (-1131.003, 224.635) and (-1107.056, 173.287); A3 r 110 centre (-1144.623, 187.025) between (-1246.2, 229.24) and (-1176.471, 81.737); A4 r 105 centre (-1189.112, 597.66) between (-1223.594, 696.836) and (-1284.272, 553.28); A5 r 408 centre (-630.824, 398) between (-943.37, 660.257) and (-630.824, -10); A6 r 418 centre (-630.824, 398) between (-739.856, -5.529) and (-630.824, -20); A7 r 398 centre (-630.824, 398) between (-935.709, 653.829) and (-630.824, 0); A8 r 37.5 centre (-999.773, 31.971) between (-1033.759, 16.121) and (-999.773, -5.529); A9 r 10 centre (-434.989, 1168.072) between (-429.989, 1159.412) and (-425.141, 1166.336); A10 r 20 centre (-434.989, 1168.072) between (-424.989, 1150.752) and (-415.292, 1164.599); A11 r 40 centre (-1144.623, 187.025) between (-1107.056, 173.287) and (-1131.003, 224.635); 1 further point
    constraints: 66 end point, 23 point on circle, 15 point on line, 13 centre point
  sketch "FrontBucket_5"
